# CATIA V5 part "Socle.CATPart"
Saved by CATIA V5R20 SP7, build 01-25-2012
Part number: Socle
Bounding box of the stored display mesh (mm): x -80 to 80, y -210 to 110.267, z -10 to 130
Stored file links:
  D:\thinkmotion-MPB\Dropbox\CIAO82010_JCF\SAINT-AIME\0558-SaintAime\CAO2\CAO\Socle.CATPart
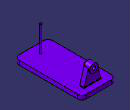
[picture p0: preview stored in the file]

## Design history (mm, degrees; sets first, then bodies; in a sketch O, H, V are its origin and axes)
Set1
  Plane1: type Offset, RefPlane zx-plane, Offset 70
Body1 (main body)
  Sketch1 on xy-plane, origin (0, 0, 0), H (1, 0, 0), V (0, 1, 0)
    line L1 (-56, 210) -> (56, 210)
    line L2 (80, 186) -> (80, -186)
    line L3 (56, -210) -> (-56, -210)
    line L4 (-80, -186) -> (-80, 186)
    arc A1 centre (-56, 186) radius 24 from (-80, 186) to (-56, 210) cw
    arc A2 centre (56, 186) radius 24 from (80, 186) to (56, 210) ccw
    arc A3 centre (56, -186) radius 24 from (80, -186) to (56, -210) cw
    arc A4 centre (-56, -186) radius 24 from (-56, -210) to (-80, -186) cw
    distance L1 L3 = 420
    distance L2 L4 = 160
    radius A1 = 24
    radius A2 = 24
    radius A3 = 24
    radius A4 = 24
    horizontal: L1 H, L3 H
    vertical: L2 V, L4 V
    symmetry: L4 L2 V, L1 L3 H
    tangency: A1 L4, A1 L1, A2 L2, A2 L1, A3 L2, A3 L3, A4 L3, A4 L4
  Pad1: profile Sketch1, direction (0, 0, 1), length 10, mirrored extent
  Sketch2 on Plane1, origin (0, 70, 0), H (-1, 0, 0), V (0, 0, 1)
    line L1 (-40, 10) -> (-19.1754, 80.2586)
    arc A1 centre (0, 74.575) radius 20 from (-19.1754, 80.2586) to (19.1754, 80.2586) cw
    point P3 (0, 74.575)
    line L2 (19.1754, 80.2586) -> (40, 10)
    line L3 (40, 10) -> (-40, 10)
    reference projected line E1 (-56, 10) -> (56, 10) from edge [face of Pad1 from Sketch1.L1 | end face of Pad1]
    length L3 = 80
    radius A1 = 20
    distance P3 L3 = 64.575
    tangency: A1 L1, L2 A1
    horizontal: L3 H
    coincidence: L3 E1
    symmetry: L1 L2 V
  Pad2: profile Sketch2, direction (0, 1, 0), length 10, mirrored extent
  Body2
    Sketch3 on Plane1, origin (0, 70, 0), H (-1, 0, 0), V (0, 0, 1)
      circle A1 centre (0, 74.575) radius 20
      point P1 (0, 74.575)
      reference projected arc E1 centre (0, 74.575) radius 20 from (19.2836, 79.8799) to (-19.2836, 79.8799) ccw from edge [face of Pad2 from Sketch2.A1 | end face of Pad2]
      circle A2 centre (0, 74.575) radius 7.5
      radius A2 = 7.5
      coincidence: P1 V, A1 E1
    Pad3: profile Sketch3, direction (0, 1, 0), length 17, mirrored extent
  Trim1: tool Body2, faces to keep face of Pad2 from Sketch2.L2; face of Pad2 from Sketch2.L1
  Sketch4 on end face of Pad1, origin (0, 0, 10), H (1, 0, 0), V (0, 1, 0)
    circle A1 centre (0, -165.605) radius 5
    point P1 (0, -165.605)
    radius A1 = 5
    distance H P1 = 165.605
    coincidence: P1 V
  Pad4: profile Sketch4, direction (0, 0, 1), length 120
  Chamfer1: length 6, angle 45, on edge [start face of Pad3 | face of Pad2]
  Fillet1: radius 2, on edge [end face of Pad1 | end face of Pad2]; edge [end face of Pad1 | face of Pad2 from Sketch2.L1]; edge [start face of Pad2 | end face of Pad1]; edge [face of Pad2 from Sketch2.L2 | end face of Pad1]
  Sketch5 on end face of Pad1, origin (0, 0, 10), H (1, 0, 0), V (0, 1, 0)
    line L1 (-142.7463, 235.012) -> (128.568, 235.012)
    line L2 (128.568, 235.012) -> (128.568, 110.2675)
    line L3 (128.568, 110.2675) -> (-142.7463, 110.2675)
    line L4 (-142.7463, 110.2675) -> (-142.7463, 235.012)
    horizontal: L1 H, L3 H
    vertical: L2 V, L4 V
  Pocket1: profile Sketch5, direction (0, 0, -1), length 120
  Fillet2: radius 20, on edge [face of Pad1 from Sketch1.L2 | face of Pocket1 from Sketch5.L3]; edge [face of Pocket1 from Sketch5.L3 | face of Pad1 from Sketch1.L4]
